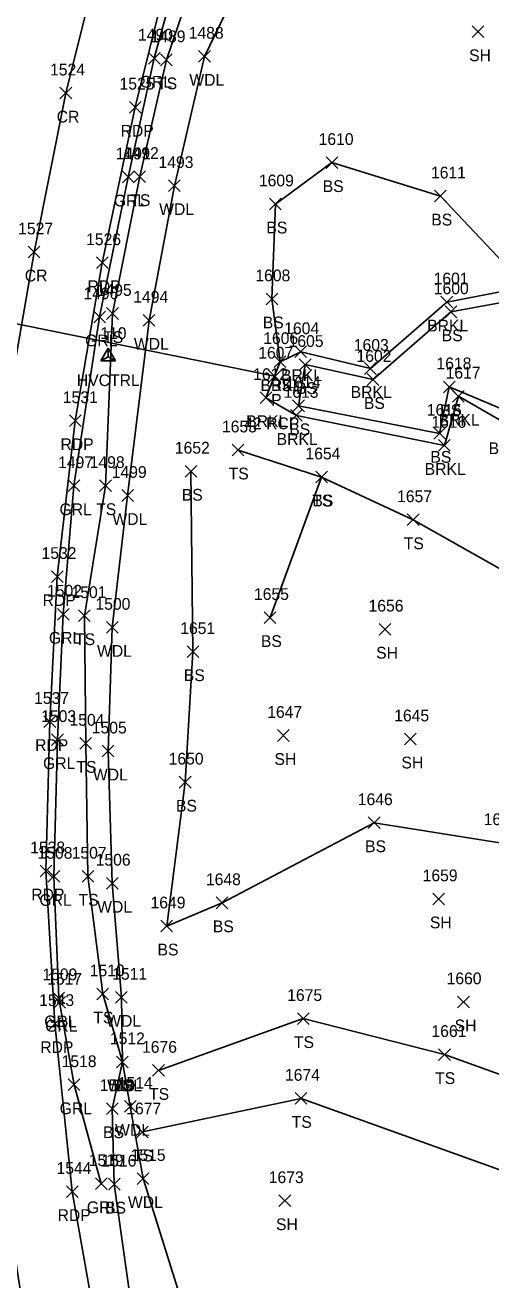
# Model space of a CAD drawing. Extents: x 1885914 to 1887218, y 756253 to 760620.
# Drawn here: x 1886440.2 to 1886519.5, y 759574 to 759787.4 of the extents above; entities that cross this region are included whole.
import ezdxf

# ---------------------------------------------------------------- set-up
doc = ezdxf.new("R2010")
doc.units = 0
for name, color, linetype in [('C_A', 7, 'Continuous'), ('C_I', 7, 'Continuous'), ('CPSM', 7, 'Continuous'), ('D_A', 7, 'Continuous'), ('D_C', 7, 'Continuous'), ('D_I', 7, 'Continuous'), ('D_TIC', 7, 'Continuous'), ('DCP', 7, 'Continuous'), ('L_A', 7, 'Continuous'), ('L_I', 7, 'Continuous'), ('L_TIC', 7, 'Continuous'), ('LAWA', 7, 'Continuous'), ('LAWE', 7, 'Continuous'), ('LELB', 7, 'Continuous'), ('P_A', 7, 'Continuous'), ('P_I', 7, 'Continuous'), ('P_TIC', 7, 'Continuous'), ('PET', 7, 'Continuous'), ('PRC', 7, 'Continuous'), ('R_A', 7, 'Continuous'), ('R_I', 7, 'Continuous'), ('R_TIC', 7, 'Continuous'), ('RGR', 7, 'Continuous')]:
    doc.layers.add(name, color=color, linetype=linetype)

msp = doc.modelspace()

# ---------------------------------------------------------------- linework, layer by layer
at = {"layer": 'CPSM'}
for p, q in [((1886453.09, 759730.28), (1886454.34, 759732.45)), ((1886453.09, 759730.28), (1886454.34, 759731)), ((1886455.59, 759730.28), (1886454.34, 759732.45)), ((1886454.34, 759731), (1886454.34, 759732.45)), ((1886454.34, 759731), (1886454.34, 759731)), ((1886454.34, 759731), (1886455.59, 759730.28)), ((1886453.09, 759730.28), (1886455.59, 759730.28))]:
    msp.add_line(p, q, dxfattribs=at)
at = {"layer": 'D_TIC'}
for points in [[(1886481.74, 759726.67), (1886483.74, 759728.67)], [(1886483.74, 759726.67), (1886481.74, 759728.67)]]:
    msp.add_lwpolyline(points, dxfattribs=at)
at = {"layer": 'DCP'}
msp.add_lwpolyline([(1886482.74, 759727.67), (1886405.41, 759743.36)], dxfattribs=at)
at = {"layer": 'L_TIC'}
for points in [[(1886516.33, 759785.25), (1886518.33, 759787.25)], [(1886518.33, 759785.25), (1886516.33, 759787.25)], [(1886463.28, 759780.47), (1886465.28, 759782.47)], [(1886465.28, 759780.47), (1886463.28, 759782.47)], [(1886469.77, 759781.07), (1886471.77, 759783.07)], [(1886471.77, 759781.07), (1886469.77, 759783.07)], [(1886491.46, 759763), (1886493.46, 759765)], [(1886493.46, 759763), (1886491.46, 759765)], [(1886458.74, 759760.62), (1886460.74, 759762.62)], [(1886460.74, 759760.62), (1886458.74, 759762.62)], [(1886464.64, 759759.08), (1886466.64, 759761.08)], [(1886466.64, 759759.08), (1886464.64, 759761.08)], [(1886509.94, 759757.31), (1886511.94, 759759.31)], [(1886511.94, 759757.31), (1886509.94, 759759.31)], [(1886509.94, 759757.31), (1886511.94, 759759.31)], [(1886511.94, 759757.31), (1886509.94, 759759.31)], [(1886481.85, 759755.96), (1886483.85, 759757.96)], [(1886483.85, 759755.96), (1886481.85, 759757.96)], [(1886481.25, 759739.82), (1886483.25, 759741.82)], [(1886483.25, 759739.82), (1886481.25, 759741.82)], [(1886511.03, 759739.29), (1886513.03, 759741.29)], [(1886513.03, 759739.29), (1886511.03, 759741.29)], [(1886454.11, 759737.34), (1886456.11, 759739.34)], [(1886456.11, 759737.34), (1886454.11, 759739.34)], [(1886511.72, 759737.63), (1886513.72, 759739.63)], [(1886513.72, 759737.63), (1886511.72, 759739.63)], [(1886460.33, 759736.18), (1886462.33, 759738.18)], [(1886462.33, 759736.18), (1886460.33, 759738.18)], [(1886486.16, 759730.84), (1886488.16, 759732.84)], [(1886488.16, 759730.84), (1886486.16, 759732.84)], [(1886482.64, 759729.15), (1886484.64, 759731.15)], [(1886484.64, 759729.15), (1886482.64, 759731.15)], [(1886482.64, 759729.15), (1886484.64, 759731.15)], [(1886484.64, 759729.15), (1886482.64, 759731.15)], [(1886486.91, 759728.66), (1886488.91, 759730.66)], [(1886488.91, 759728.66), (1886486.91, 759730.66)], [(1886498.01, 759728), (1886500.01, 759730)], [(1886500.01, 759728), (1886498.01, 759730)], [(1886498.47, 759726.12), (1886500.47, 759728.12)], [(1886500.47, 759726.12), (1886498.47, 759728.12)], [(1886511.44, 759724.86), (1886513.44, 759726.86)], [(1886513.44, 759724.86), (1886511.44, 759726.86)], [(1886480.22, 759723.03), (1886482.22, 759725.03)], [(1886482.22, 759723.03), (1886480.22, 759725.03)], [(1886512.99, 759723.28), (1886514.99, 759725.28)], [(1886514.99, 759723.28), (1886512.99, 759725.28)], [(1886485.77, 759721.65), (1886487.77, 759723.65)], [(1886487.77, 759721.65), (1886485.77, 759723.65)], [(1886485.41, 759720.01), (1886487.41, 759722.01)], [(1886487.41, 759720.01), (1886485.41, 759722.01)], [(1886509.79, 759716.96), (1886511.79, 759718.96)], [(1886511.79, 759716.96), (1886509.79, 759718.96)], [(1886475.48, 759714.13), (1886477.48, 759716.13)], [(1886477.48, 759714.13), (1886475.48, 759716.13)], [(1886510.62, 759714.91), (1886512.62, 759716.91)], [(1886512.62, 759714.91), (1886510.62, 759716.91)], [(1886467.46, 759710.52), (1886469.46, 759712.52)], [(1886469.46, 759710.52), (1886467.46, 759712.52)], [(1886489.7, 759709.54), (1886491.7, 759711.54)], [(1886491.7, 759709.54), (1886489.7, 759711.54)], [(1886489.7, 759709.54), (1886491.7, 759711.54)], [(1886491.7, 759709.54), (1886489.7, 759711.54)], [(1886452.91, 759708.07), (1886454.91, 759710.07)], [(1886454.91, 759708.07), (1886452.91, 759710.07)], [(1886456.67, 759706.39), (1886458.67, 759708.39)], [(1886458.67, 759706.39), (1886456.67, 759708.39)], [(1886505.3, 759702.27), (1886507.3, 759704.27)], [(1886507.3, 759702.27), (1886505.3, 759704.27)], [(1886449.32, 759685.96), (1886451.32, 759687.96)], [(1886451.32, 759685.96), (1886449.32, 759687.96)], [(1886454.06, 759683.97), (1886456.06, 759685.97)], [(1886456.06, 759683.97), (1886454.06, 759685.97)], [(1886480.93, 759685.64), (1886482.93, 759687.64)], [(1886482.93, 759685.64), (1886480.93, 759687.64)], [(1886500.5, 759683.66), (1886502.5, 759685.66)], [(1886502.5, 759683.66), (1886500.5, 759685.66)], [(1886467.81, 759679.84), (1886469.81, 759681.84)], [(1886469.81, 759679.84), (1886467.81, 759681.84)], [(1886483.19, 759665.59), (1886485.19, 759667.59)], [(1886485.19, 759665.59), (1886483.19, 759667.59)], [(1886504.81, 759664.99), (1886506.81, 759666.99)], [(1886506.81, 759664.99), (1886504.81, 759666.99)], [(1886449.55, 759664.25), (1886451.55, 759666.25)], [(1886451.55, 759664.25), (1886449.55, 759666.25)], [(1886453.35, 759662.94), (1886455.35, 759664.94)], [(1886455.35, 759662.94), (1886453.35, 759664.94)], [(1886466.48, 759657.65), (1886468.48, 759659.65)], [(1886468.48, 759657.65), (1886466.48, 759659.65)], [(1886498.66, 759650.75), (1886500.66, 759652.75)], [(1886500.66, 759650.75), (1886498.66, 759652.75)], [(1886449.92, 759641.65), (1886451.92, 759643.65)], [(1886451.92, 759641.65), (1886449.92, 759643.65)], [(1886454.07, 759640.46), (1886456.07, 759642.46)], [(1886456.07, 759640.46), (1886454.07, 759642.46)], [(1886472.75, 759637.14), (1886474.75, 759639.14)], [(1886474.75, 759637.14), (1886472.75, 759639.14)], [(1886509.66, 759637.8), (1886511.66, 759639.8)], [(1886511.66, 759637.8), (1886509.66, 759639.8)], [(1886463.33, 759633.19), (1886465.33, 759635.19)], [(1886465.33, 759633.19), (1886463.33, 759635.19)], [(1886452.45, 759621.64), (1886454.45, 759623.64)], [(1886454.45, 759621.64), (1886452.45, 759623.64)], [(1886455.61, 759621.06), (1886457.61, 759623.06)], [(1886457.61, 759621.06), (1886455.61, 759623.06)], [(1886513.87, 759620.29), (1886515.87, 759622.29)], [(1886515.87, 759620.29), (1886513.87, 759622.29)], [(1886486.59, 759617.45), (1886488.59, 759619.45)], [(1886488.59, 759617.45), (1886486.59, 759619.45)], [(1886510.63, 759611.33), (1886512.63, 759613.33)], [(1886512.63, 759611.33), (1886510.63, 759613.33)], [(1886455.79, 759610.09), (1886457.79, 759612.09)], [(1886457.79, 759610.09), (1886455.79, 759612.09)], [(1886455.79, 759610.09), (1886457.79, 759612.09)], [(1886457.79, 759610.09), (1886455.79, 759612.09)], [(1886455.79, 759610.09), (1886457.79, 759612.09)], [(1886457.79, 759610.09), (1886455.79, 759612.09)], [(1886461.93, 759608.64), (1886463.93, 759610.64)], [(1886463.93, 759608.64), (1886461.93, 759610.64)], [(1886486.21, 759603.88), (1886488.21, 759605.88)], [(1886488.21, 759603.88), (1886486.21, 759605.88)], [(1886454.06, 759602.13), (1886456.06, 759604.13)], [(1886456.06, 759602.13), (1886454.06, 759604.13)], [(1886457.12, 759602.52), (1886459.12, 759604.52)], [(1886459.12, 759602.52), (1886457.12, 759604.52)], [(1886459.19, 759598.17), (1886461.19, 759600.17)], [(1886461.19, 759598.17), (1886459.19, 759600.17)], [(1886459.31, 759590.25), (1886461.31, 759592.25)], [(1886461.31, 759590.25), (1886459.31, 759592.25)], [(1886454.4, 759589.3), (1886456.4, 759591.3)], [(1886456.4, 759589.3), (1886454.4, 759591.3)], [(1886483.45, 759586.48), (1886485.45, 759588.48)], [(1886485.45, 759586.48), (1886483.45, 759588.48)]]:
    msp.add_lwpolyline(points, dxfattribs=at)
at = {"layer": 'LAWA'}
msp.add_lwpolyline([(1886523.26, 759869.7), (1886507.15, 759897.34), (1886498.06, 759871.13), (1886491.77, 759845.85), (1886483.62, 759823.8), (1886481.1, 759806.96), (1886479.96, 759798.66), (1886477.13, 759795.21), (1886470.77, 759782.07), (1886465.64, 759760.08), (1886461.33, 759737.18), (1886457.67, 759707.39), (1886455.06, 759684.97), (1886454.35, 759663.94), (1886455.07, 759641.46), (1886456.61, 759622.06), (1886456.79, 759611.09), (1886458.12, 759603.52), (1886460.31, 759591.25), (1886468.58, 759565.01)], dxfattribs=at)
at = {"layer": 'LAWE'}
msp.add_lwpolyline([(1886525.52, 759742.88), (1886512.03, 759740.29), (1886499.01, 759729), (1886487.16, 759731.84), (1886483.64, 759730.15), (1886481.22, 759724.03), (1886486.41, 759721.01), (1886511.62, 759715.91), (1886513.99, 759724.28), (1886522.49, 759719.43)], dxfattribs=at)
at = {"layer": 'LELB'}
for points in [[(1886527.64, 759964.02), (1886508.85, 759921.99), (1886500.17, 759900.4), (1886490.04, 759873.78), (1886482, 759847.55), (1886476.31, 759825.69), (1886474.25, 759817.99), (1886471.86, 759803.75), (1886464.28, 759781.47), (1886459.74, 759761.62), (1886455.11, 759738.34), (1886453.91, 759709.07), (1886450.32, 759686.96), (1886450.55, 759665.25), (1886450.92, 759642.65), (1886453.45, 759622.64), (1886456.79, 759611.09)], [(1886483.64, 759730.15), (1886482.25, 759740.82), (1886482.85, 759756.96), (1886492.46, 759764), (1886510.94, 759758.31)], [(1886525.52, 759742.88), (1886510.94, 759758.31)], [(1886525.4, 759740.93), (1886512.72, 759738.63), (1886499.47, 759727.12), (1886487.91, 759729.66), (1886486.77, 759722.65), (1886510.79, 759717.96), (1886512.44, 759725.86), (1886524.57, 759720.77)], [(1886476.48, 759715.13), (1886490.7, 759710.54), (1886506.3, 759703.27), (1886522.17, 759694.33)], [(1886647.18, 759601.26), (1886612.58, 759616.96), (1886585.88, 759628.41), (1886552.89, 759637.57), (1886521.04, 759648.35), (1886499.66, 759651.75), (1886473.75, 759638.14), (1886464.33, 759634.19), (1886467.48, 759658.65), (1886468.81, 759680.84), (1886468.46, 759711.52)], [(1886490.7, 759710.54), (1886481.93, 759686.64)], [(1886611.24, 759576.51), (1886511.63, 759612.33), (1886487.59, 759618.45), (1886462.93, 759609.64)], [(1886456.79, 759611.09), (1886455.06, 759603.13), (1886455.4, 759590.3), (1886459.57, 759560.59), (1886463.53, 759534.18), (1886472.77, 759498.14), (1886480.93, 759466.98), (1886488.08, 759436.33), (1886497.78, 759399.81), (1886507.53, 759360.15), (1886514.24, 759339.59)], [(1886580.36, 759581.73), (1886548.99, 759588.59), (1886527.52, 759590.44), (1886487.21, 759604.88), (1886460.19, 759599.17)]]:
    msp.add_lwpolyline(points, dxfattribs=at)
at = {"layer": 'P_TIC'}
for points in [[(1886446.16, 759774.82), (1886448.16, 759776.82)], [(1886448.16, 759774.82), (1886446.16, 759776.82)], [(1886457.99, 759772.42), (1886459.99, 759774.42)], [(1886459.99, 759772.42), (1886457.99, 759774.42)], [(1886440.74, 759747.8), (1886442.74, 759749.8)], [(1886442.74, 759747.8), (1886440.74, 759749.8)], [(1886452.36, 759745.97), (1886454.36, 759747.97)], [(1886454.36, 759745.97), (1886452.36, 759747.97)], [(1886447.76, 759719.11), (1886449.76, 759721.11)], [(1886449.76, 759719.11), (1886447.76, 759721.11)], [(1886444.71, 759692.61), (1886446.71, 759694.61)], [(1886446.71, 759692.61), (1886444.71, 759694.61)], [(1886443.44, 759667.96), (1886445.44, 759669.96)], [(1886445.44, 759667.96), (1886443.44, 759669.96)], [(1886442.78, 759642.55), (1886444.78, 759644.55)], [(1886444.78, 759642.55), (1886442.78, 759644.55)], [(1886444.31, 759616.59), (1886446.31, 759618.59)], [(1886446.31, 759616.59), (1886444.31, 759618.59)], [(1886447.26, 759588.04), (1886449.26, 759590.04)], [(1886449.26, 759588.04), (1886447.26, 759590.04)]]:
    msp.add_lwpolyline(points, dxfattribs=at)
at = {"layer": 'PET'}
msp.add_lwpolyline([(1886526.14, 759964.92), (1886507.07, 759922.75), (1886498.17, 759900.86), (1886488.16, 759874.15), (1886479.62, 759848.04), (1886473, 759827.05), (1886466.37, 759803.11), (1886458.99, 759773.42), (1886453.36, 759746.97), (1886448.76, 759720.11), (1886445.71, 759693.61), (1886444.44, 759668.96), (1886443.78, 759643.55), (1886445.31, 759617.59), (1886448.26, 759589.04), (1886453.63, 759558.69), (1886458.27, 759533.55), (1886466.8, 759496), (1886474.35, 759464.49), (1886481.64, 759434.54), (1886491.18, 759398.8), (1886502.68, 759358.39), (1886508.23, 759337.95)], dxfattribs=at)
at = {"layer": 'PRC'}
msp.add_lwpolyline([(1886516.05, 759969.43), (1886496.99, 759926.69), (1886487.66, 759904.2), (1886477.68, 759877.96), (1886468.59, 759851.92), (1886461.77, 759829.93), (1886454.6, 759805.62), (1886447.16, 759775.82), (1886441.74, 759748.8), (1886436.89, 759720.56), (1886434.02, 759695.25), (1886432.32, 759669.09), (1886432.26, 759642.82), (1886433.77, 759616.6), (1886436.98, 759587.84), (1886441.74, 759556.93), (1886446.53, 759531.43), (1886454.86, 759493.34), (1886462.57, 759461.76), (1886470.69, 759431.8), (1886480.02, 759395.82), (1886491.53, 759354.96), (1886496.99, 759335.08)], dxfattribs=at)
at = {"layer": 'R_TIC'}
for points in [[(1886461.22, 759780.75), (1886463.22, 759782.75)], [(1886463.22, 759780.75), (1886461.22, 759782.75)], [(1886456.79, 759760.55), (1886458.79, 759762.55)], [(1886458.79, 759760.55), (1886456.79, 759762.55)], [(1886451.9, 759736.77), (1886453.9, 759738.77)], [(1886453.9, 759736.77), (1886451.9, 759738.77)], [(1886447.54, 759708.05), (1886449.54, 759710.05)], [(1886449.54, 759708.05), (1886447.54, 759710.05)], [(1886445.73, 759686.2), (1886447.73, 759688.2)], [(1886447.73, 759686.2), (1886445.73, 759688.2)], [(1886444.74, 759664.88), (1886446.74, 759666.88)], [(1886446.74, 759664.88), (1886444.74, 759666.88)], [(1886444.12, 759641.63), (1886446.12, 759643.63)], [(1886446.12, 759641.63), (1886444.12, 759643.63)], [(1886444.94, 759620.97), (1886446.94, 759622.97)], [(1886446.94, 759620.97), (1886444.94, 759622.97)], [(1886445.09, 759620.22), (1886447.09, 759622.22)], [(1886447.09, 759620.22), (1886445.09, 759622.22)], [(1886447.56, 759606.2), (1886449.56, 759608.2)], [(1886449.56, 759606.2), (1886447.56, 759608.2)], [(1886452.2, 759589.37), (1886454.2, 759591.37)], [(1886454.2, 759589.37), (1886452.2, 759591.37)]]:
    msp.add_lwpolyline(points, dxfattribs=at)
at = {"layer": 'RGR'}
msp.add_lwpolyline([(1886477.91, 759824.72), (1886474.25, 759817.99), (1886468.53, 759804.81), (1886462.22, 759781.75), (1886457.79, 759761.55), (1886452.9, 759737.77), (1886448.54, 759709.05), (1886446.73, 759687.2), (1886445.74, 759665.88), (1886445.12, 759642.63), (1886445.94, 759621.97), (1886446.09, 759621.22), (1886448.56, 759607.2), (1886453.2, 759590.37)], dxfattribs=at)

# ---------------------------------------------------------------- texts
at = {"layer": 'C_A'}
msp.add_text('HVCTRL', height=2, dxfattribs=at).set_placement((1886449.03, 759726))
at = {"layer": 'C_I'}
msp.add_text('110', height=2, dxfattribs=at).set_placement((1886453.02, 759734))
at = {"layer": 'D_A'}
msp.add_text('P', height=2, dxfattribs=at).set_placement((1886482.12, 759722.67))
at = {"layer": 'D_C'}
msp.add_text('42 RCP', height=2, dxfattribs=at).set_placement((1886477.54, 759718.67))
at = {"layer": 'D_I'}
msp.add_text('1607', height=2, dxfattribs=at).set_placement((1886479.92, 759730.67))
at = {"layer": 'L_A'}
for s, p in [('SH', (1886515.82, 759781.25)), ('TS', (1886462.69, 759776.47)), ('WDL', (1886468.19, 759777.07)), ('BS', (1886490.9, 759759)), ('TS', (1886458.14, 759756.62)), ('WDL', (1886463.05, 759755.08)), ('BS', (1886509.38, 759753.31)), ('BS', (1886509.38, 759753.31)), ('BS', (1886481.3, 759751.96)), ('BS', (1886480.69, 759735.82)), ('BRKL', (1886508.68, 759735.29)), ('TS', (1886453.52, 759733.34)), ('BS', (1886511.16, 759733.63)), ('WDL', (1886458.75, 759732.18)), ('BRKL', (1886483.8, 759726.84)), ('BRKL', (1886480.29, 759725.15)), ('BS', (1886482.08, 759725.15)), ('BS', (1886486.35, 759724.66)), ('BRKL', (1886495.66, 759724)), ('BS', (1886497.91, 759722.12)), ('BS', (1886510.89, 759720.86)), ('BRKL', (1886477.87, 759719.03)), ('BRKL', (1886510.63, 759719.28)), ('BRKL', (1886483.05, 759716.01)), ('BS', (1886485.21, 759717.65)), ('BRKL', (1886519.14, 759714.43)), ('BS', (1886509.23, 759712.96)), ('TS', (1886474.88, 759710.13)), ('BRKL', (1886508.26, 759710.91)), ('BS', (1886466.9, 759706.52)), ('TS', (1886489.11, 759705.54)), ('BS', (1886489.14, 759705.54)), ('TS', (1886452.32, 759704.07)), ('WDL', (1886455.09, 759702.39)), ('TS', (1886504.7, 759698.27)), ('TS', (1886448.73, 759681.96)), ('WDL', (1886452.47, 759679.97)), ('BS', (1886480.37, 759681.64)), ('SH', (1886499.99, 759679.66)), ('BS', (1886467.25, 759675.84)), ('SH', (1886482.68, 759661.59)), ('SH', (1886504.3, 759660.99)), ('TS', (1886448.96, 759660.25)), ('WDL', (1886451.77, 759658.94)), ('BS', (1886465.92, 759653.65)), ('BS', (1886498.11, 759646.75)), ('TS', (1886449.33, 759637.65)), ('WDL', (1886452.49, 759636.46)), ('BS', (1886472.19, 759633.14)), ('SH', (1886509.15, 759633.8)), ('BS', (1886462.77, 759629.19)), ('TS', (1886451.85, 759617.64)), ('WDL', (1886454.03, 759617.06)), ('SH', (1886513.36, 759616.29)), ('TS', (1886486, 759613.45)), ('TS', (1886510.04, 759607.33)), ('WDL', (1886454.2, 759606.09)), ('TS', (1886455.19, 759606.09)), ('BS', (1886455.23, 759606.09)), ('TS', (1886461.33, 759604.64)), ('WDL', (1886455.54, 759598.52)), ('TS', (1886485.62, 759599.88)), ('BS', (1886453.5, 759598.13)), ('TS', (1886458.6, 759594.17)), ('WDL', (1886457.73, 759586.25)), ('BS', (1886453.84, 759585.3)), ('SH', (1886482.94, 759582.48))]:
    msp.add_text(s, height=2, dxfattribs=at).set_placement(p)
at = {"layer": 'L_I'}
for s, p in [('1489', (1886461.58, 759784.47)), ('1488', (1886468.08, 759785.07)), ('1610', (1886490.2, 759767)), ('1492', (1886457.04, 759764.62)), ('1493', (1886462.94, 759763.08)), ('1611', (1886509.33, 759761.31)), ('1611', (1886509.33, 759761.31)), ('1609', (1886480.03, 759759.96)), ('1608', (1886479.43, 759743.82)), ('1601', (1886509.78, 759743.29)), ('1600', (1886509.81, 759741.63)), ('1495', (1886452.42, 759741.34)), ('1494', (1886458.64, 759740.18)), ('1606', (1886480.77, 759733.15)), ('1606', (1886480.77, 759733.15)), ('1604', (1886484.34, 759734.84)), ('1605', (1886485.09, 759732.66)), ('1603', (1886496.19, 759732)), ('1602', (1886496.65, 759730.12)), ('1618', (1886510.27, 759728.86)), ('1612', (1886479.05, 759727.03)), ('1617', (1886511.82, 759727.28)), ('1614', (1886484.59, 759725.65)), ('1613', (1886484.23, 759724.01)), ('1615', (1886508.62, 759720.96)), ('1653', (1886473.74, 759718.13)), ('1616', (1886509.39, 759718.91)), ('1652', (1886465.72, 759714.52)), ('1498', (1886451.22, 759712.07)), ('1654', (1886487.96, 759713.54)), ('1654', (1886487.96, 759713.54)), ('1499', (1886454.97, 759710.39)), ('1657', (1886503.56, 759706.27)), ('1501', (1886448.12, 759689.96)), ('1655', (1886479.19, 759689.64)), ('1500', (1886452.2, 759687.97)), ('1656', (1886498.7, 759687.66)), ('1651', (1886466.64, 759683.84)), ('1647', (1886481.45, 759669.59)), ('1645', (1886503.07, 759668.99)), ('1504', (1886447.78, 759668.25)), ('1505', (1886451.58, 759666.94)), ('1650', (1886464.66, 759661.65)), ('1646', (1886496.87, 759654.75)), ('1644', (1886518.3, 759651.35)), ('1507', (1886448.15, 759645.65)), ('1506', (1886452.24, 759644.46)), ('1648', (1886471.01, 759641.14)), ('1659', (1886507.91, 759641.8)), ('1649', (1886461.58, 759637.19)), ('1510', (1886451.23, 759625.64)), ('1511', (1886455.05, 759625.06)), ('1660', (1886511.99, 759624.29)), ('1675', (1886484.85, 759621.45)), ('1512', (1886454.66, 759614.09)), ('1512', (1886454.66, 759614.09)), ('1512', (1886454.66, 759614.09)), ('1661', (1886509.41, 759615.33)), ('1676', (1886460.13, 759612.64)), ('1674', (1886484.47, 759607.88)), ('1513', (1886452.94, 759606.13)), ('1514', (1886456, 759606.52)), ('1677', (1886457.45, 759602.17)), ('1515', (1886458.19, 759594.25)), ('1516', (1886453.22, 759593.3)), ('1673', (1886481.71, 759590.48))]:
    msp.add_text(s, height=2, dxfattribs=at).set_placement(p)
at = {"layer": 'P_A'}
for s, p in [('CR', (1886445.6, 759770.82)), ('RDP', (1886456.48, 759768.42)), ('CR', (1886440.17, 759743.8)), ('RDP', (1886450.85, 759741.97)), ('RDP', (1886446.25, 759715.11)), ('RDP', (1886443.2, 759688.61)), ('RDP', (1886441.93, 759663.96)), ('RDP', (1886441.27, 759638.55)), ('RDP', (1886442.8, 759612.59)), ('RDP', (1886445.75, 759584.04))]:
    msp.add_text(s, height=2, dxfattribs=at).set_placement(p)
at = {"layer": 'P_I'}
for s, p in [('1524', (1886444.47, 759778.82)), ('1525', (1886456.3, 759776.42)), ('1527', (1886439.04, 759751.8)), ('1526', (1886450.61, 759749.97)), ('1531', (1886446.64, 759723.11)), ('1532', (1886443.02, 759696.61)), ('1537', (1886441.75, 759671.96)), ('1538', (1886441.09, 759646.55)), ('1543', (1886442.62, 759620.59)), ('1544', (1886445.57, 759592.04))]:
    msp.add_text(s, height=2, dxfattribs=at).set_placement(p)
at = {"layer": 'R_A'}
for p in [(1886459.76, 759776.75), (1886455.33, 759756.55), (1886450.45, 759732.77), (1886446.08, 759704.05), (1886444.28, 759682.2), (1886443.28, 759660.88), (1886442.66, 759637.63), (1886443.48, 759616.97), (1886443.64, 759616.22), (1886446.11, 759602.2), (1886450.74, 759585.37)]:
    msp.add_text('GRL', height=2, dxfattribs=at).set_placement(p)
at = {"layer": 'R_I'}
for s, p in [('1490', (1886459.44, 759784.75)), ('1491', (1886455.66, 759764.55)), ('1496', (1886450.15, 759740.77)), ('1497', (1886445.85, 759712.05)), ('1502', (1886443.96, 759690.2)), ('1503', (1886442.96, 759668.88)), ('1508', (1886442.34, 759645.63)), ('1509', (1886443.16, 759624.97)), ('1517', (1886443.97, 759624.22)), ('1518', (1886446.44, 759610.2)), ('1519', (1886451.06, 759593.37))]:
    msp.add_text(s, height=2, dxfattribs=at).set_placement(p)

doc.saveas('drawing.dxf')
